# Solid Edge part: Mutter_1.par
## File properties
Sűrűség: 0,000 kg/m^3
Pontosság: 0,990
Author: ahadarics
Last saved by: ahadarics
Revision: 76
Username: ahadarics
Dokumentum tartalom típus: 0
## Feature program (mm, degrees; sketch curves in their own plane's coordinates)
base feature "unnamed BaseFeature 1"
thread "unnamed Thread 1"
chamfer "Letörés_1"  SetBackValue2 = 60 deg
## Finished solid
Body 1: solid body, 23 faces, 46 edges, 24 vertices.
  Faces by surface: cone 14, plane 8, cylinder 1
  Edges by curve: spline 24, circle 16, line 6
Bounding box of the edges (mm): 4.000 x 11.547 x 10.000, from (0, -5.7735, -5) to (4, 5.7735, 5).
Cylindrical faces by radius (mm): R2.4585 x1
Conical faces (half-angle, radius in mm at the cone's reference point): 60 deg R2.4585 x1, 60 deg R3.1513 x1, 60 deg R5.3868 x12
Planar faces by outward normal: +x 1, +z 1, -x 1, -z 1, oblique 4
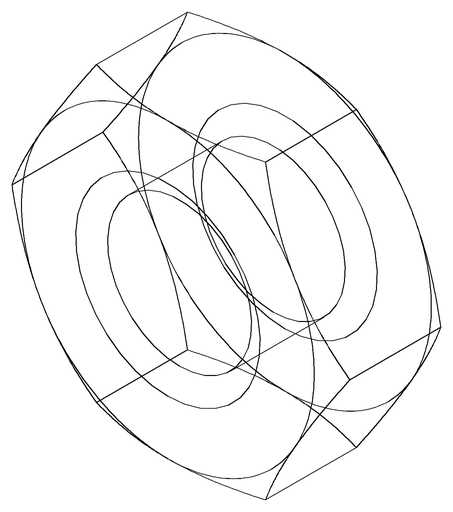
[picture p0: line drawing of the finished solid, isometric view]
